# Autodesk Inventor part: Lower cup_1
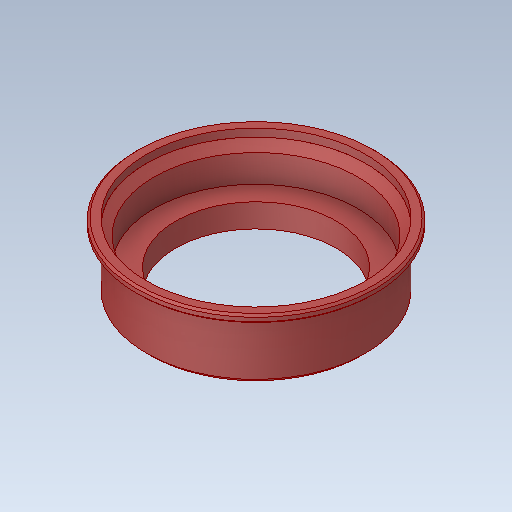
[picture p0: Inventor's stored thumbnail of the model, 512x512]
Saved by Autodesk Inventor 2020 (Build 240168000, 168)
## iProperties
Created: 2017-09
Part Number: Lower cup_1
Material: Ogólny
Document SubType Name: Modeling
Designer: Tomasz
Density: 1 g/cm^3
Appearance: Domyślna
Sending System: SolidWorks 2017
Last Author: Tomasz
Last Saved: 2017-09-17
Source: Lower cup_1
Author: Tomasz
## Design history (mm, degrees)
feature "Faza2"
feature "Wyciągnięcie proste6" [Faza]
node "Bryła1"
node "Bryła2"
